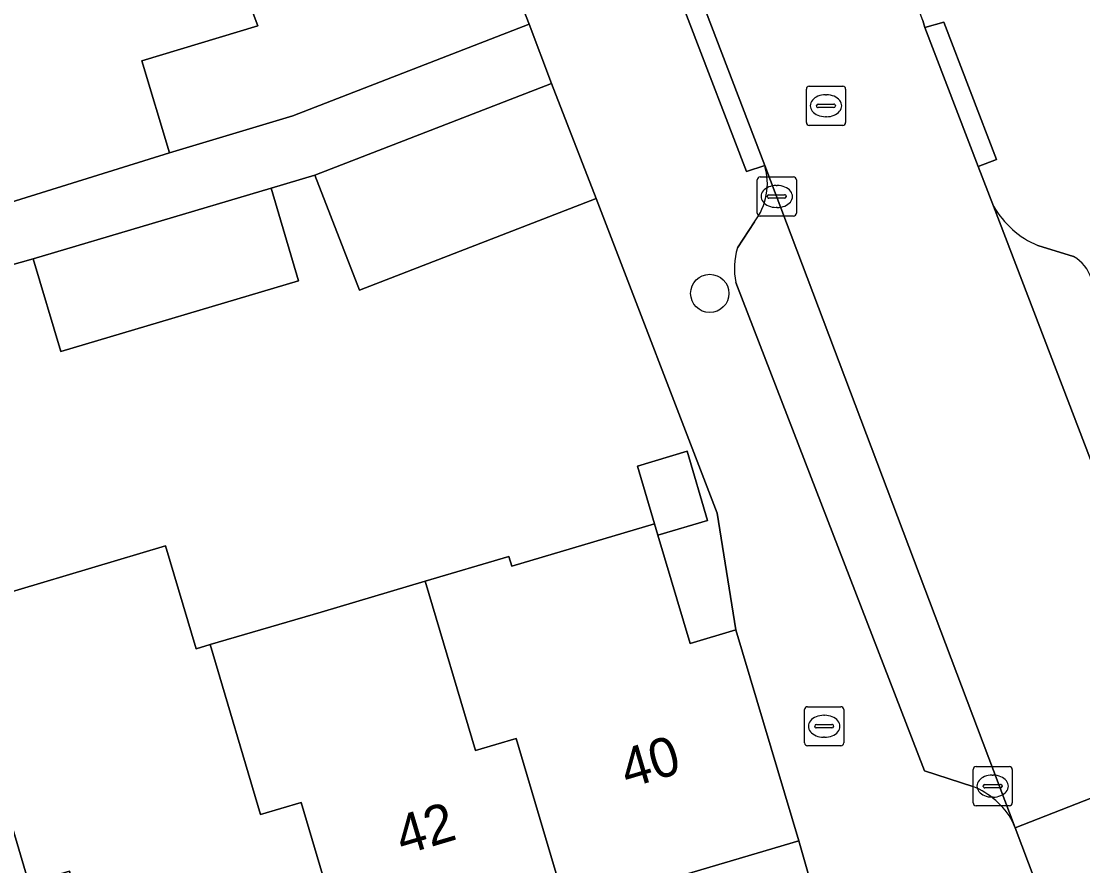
# Model space of a CAD drawing. Extents: x 162523 to 163266, y 381230 to 382050.
# Drawn here: x 162859.78 to 162886.88, y 381771.84 to 381793.41 of the extents above; entities that cross this region are included whole.
import ezdxf

# ---------------------------------------------------------------- set-up
doc = ezdxf.new("R2010")
doc.units = 0
for name, color, linetype in [('IMGEO_Boom', 7, 'Continuous'), ('IMGEO_Brandkraan', 7, 'Continuous'), ('IMGEO_Erf', 7, 'Continuous'), ('IMGEO_Kolk', 7, 'Continuous'), ('IMGEO_Muur', 7, 'Continuous'), ('IMGEO_Pand', 7, 'Continuous'), ('IMGEO_Pand_nummerreeks', 7, 'Continuous'), ('IMGEO_Parkeervlak_open', 7, 'Continuous'), ('IMGEO_Rijbaan_lokaal_open', 7, 'Continuous'), ('IMGEO_Rioolput', 7, 'Continuous'), ('IMGEO_Voetpad_open', 7, 'Continuous')]:
    doc.layers.add(name, color=color, linetype=linetype)

msp = doc.modelspace()

# ---------------------------------------------------------------- linework, layer by layer
at = {"layer": 'IMGEO_Boom'}
msp.add_circle((162877.355, 381786.459), 0.489, dxfattribs=at)
at = {"layer": 'IMGEO_Brandkraan'}
for p, q in [((162879.774, 381774.979), (162879.774, 381775.831)), ((162879.849, 381775.905), (162880.701, 381775.905)), ((162880.262, 381775.685), (162880.287, 381775.685)), ((162880.775, 381775.831), (162880.775, 381774.979)), ((162880.033, 381775.399), (162880.033, 381775.411)), ((162880.076, 381775.448), (162880.474, 381775.448)), ((162880.517, 381775.411), (162880.517, 381775.399)), ((162880.471, 381775.362), (162880.073, 381775.362)), ((162880.701, 381774.905), (162879.849, 381774.905)), ((162880.285, 381775.125), (162880.26, 381775.125))]:
    msp.add_line(p, q, dxfattribs=at)
for points in [[(162879.774, 381774.979), (162879.774, 381775.831)], [(162879.849, 381775.905), (162880.701, 381775.905)], [(162880.775, 381775.831), (162880.775, 381774.979)], [(162880.701, 381774.905), (162879.849, 381774.905)]]:
    msp.add_lwpolyline(points, dxfattribs=at)
for centre, radius, start, end in [((162879.851, 381775.829), 0.0765, 91.552, 178.448), ((162879.851, 381775.829), 0.0765, 91.552, 178.448), ((162880.699, 381775.829), 0.0765, 1.552, 88.448), ((162880.699, 381775.829), 0.0765, 1.552, 88.448), ((162880.073, 381775.408), 0.0403, 85.8775, 175.7526), ((162880.07, 381775.398), 0.0366, 178.938, 274.7102), ((162880.474, 381775.405), 0.043, 264.8664, 352.4533), ((162880.478, 381775.41), 0.0386, 1.7309, 96.639), ((162879.851, 381774.981), 0.0765, 181.552, 268.448), ((162879.851, 381774.981), 0.0765, 181.552, 268.448), ((162880.699, 381774.981), 0.0765, 271.552, 358.448), ((162880.699, 381774.981), 0.0765, 271.552, 358.448)]:
    msp.add_arc(centre, radius, start, end, dxfattribs=at)
for centre, major_axis, ratio, start_param, end_param in [((162880.261, 381775.405), (-0.387, 0.002), 0.722429, 4.712389, 7.853982), ((162880.286, 381775.405), (-0.39, 0.002), 0.717154, 1.570796, 4.712389)]:
    msp.add_ellipse(centre, major_axis=major_axis, ratio=ratio, start_param=start_param, end_param=end_param, dxfattribs=at)
at = {"layer": 'IMGEO_Erf'}
for points in [[(162858.449, 381788.462), (162863.565, 381790.046), (162862.855, 381792.401), (162865.822, 381793.297), (162865.57, 381793.947), (162871.6, 381796.286), (162865.905, 381810.851)], [(162857.816, 381778.33), (162863.463, 381780.009), (162864.243, 381777.386), (162864.6, 381777.49), (162867.434, 381778.318), (162870.088, 381779.107), (162872.226, 381779.742), (162872.299, 381779.496), (162875.944, 381780.579), (162875.507, 381782.051), (162876.776, 381782.428), (162877.3, 381780.664), (162876.031, 381780.287), (162876.852, 381777.523), (162878.023, 381777.872), (162877.543, 381780.848), (162874.457, 381788.886), (162868.417, 381786.543), (162867.278, 381789.481), (162866.157, 381789.148), (162866.86, 381786.782), (162860.792, 381784.978), (162860.088, 381787.344), (162845.75, 381783.296)], [(162880.883, 381768.073), (162879.625, 381772.482), (162873.71, 381770.724)]]:
    msp.add_lwpolyline(points, dxfattribs=at)
at = {"layer": 'IMGEO_Kolk'}
for p, q in [((162878.564, 381788.509), (162878.564, 381789.361)), ((162878.639, 381789.435), (162879.491, 381789.435)), ((162879.565, 381789.361), (162879.565, 381788.509)), ((162878.866, 381788.978), (162879.264, 381788.978)), ((162879.052, 381789.215), (162879.077, 381789.215)), ((162878.823, 381788.929), (162878.823, 381788.941)), ((162879.261, 381788.892), (162878.863, 381788.892)), ((162879.307, 381788.941), (162879.307, 381788.929)), ((162879.491, 381788.435), (162878.639, 381788.435)), ((162879.075, 381788.655), (162879.05, 381788.655)), ((162884.15, 381774.376), (162885.002, 381774.376)), ((162884.075, 381773.45), (162884.075, 381774.302)), ((162884.563, 381774.156), (162884.588, 381774.156)), ((162885.076, 381774.302), (162885.076, 381773.45)), ((162884.334, 381773.87), (162884.334, 381773.882)), ((162884.772, 381773.833), (162884.374, 381773.833)), ((162884.377, 381773.919), (162884.775, 381773.919)), ((162884.818, 381773.882), (162884.818, 381773.87)), ((162884.586, 381773.596), (162884.561, 381773.596)), ((162885.002, 381773.376), (162884.15, 381773.376))]:
    msp.add_line(p, q, dxfattribs=at)
for points in [[(162878.564, 381788.509), (162878.564, 381789.361)], [(162878.639, 381789.435), (162879.491, 381789.435)], [(162879.565, 381789.361), (162879.565, 381788.509)], [(162879.491, 381788.435), (162878.639, 381788.435)], [(162884.15, 381774.376), (162885.002, 381774.376)], [(162884.075, 381773.45), (162884.075, 381774.302)], [(162885.076, 381774.302), (162885.076, 381773.45)], [(162885.002, 381773.376), (162884.15, 381773.376)]]:
    msp.add_lwpolyline(points, dxfattribs=at)
for centre, radius, start, end in [((162878.641, 381789.359), 0.0765, 91.552, 178.448), ((162878.641, 381789.359), 0.0765, 91.552, 178.448), ((162879.489, 381789.359), 0.0765, 1.552, 88.448), ((162879.489, 381789.359), 0.0765, 1.552, 88.448), ((162878.863, 381788.938), 0.0403, 85.8775, 175.7526), ((162879.268, 381788.94), 0.0386, 1.7309, 96.639), ((162878.86, 381788.928), 0.0366, 178.938, 274.7102), ((162879.264, 381788.935), 0.043, 264.8664, 352.4533), ((162878.641, 381788.511), 0.0765, 181.552, 268.448), ((162878.641, 381788.511), 0.0765, 181.552, 268.448), ((162879.489, 381788.511), 0.0765, 271.552, 358.448), ((162879.489, 381788.511), 0.0765, 271.552, 358.448), ((162884.152, 381774.3), 0.0765, 91.552, 178.448), ((162884.152, 381774.3), 0.0765, 91.552, 178.448), ((162885, 381774.3), 0.0765, 1.552, 88.448), ((162885, 381774.3), 0.0765, 1.552, 88.448), ((162884.374, 381773.879), 0.0403, 85.8775, 175.7526), ((162884.371, 381773.869), 0.0366, 178.938, 274.7102), ((162884.775, 381773.876), 0.043, 264.8664, 352.4533), ((162884.779, 381773.881), 0.0386, 1.7309, 96.639), ((162884.152, 381773.452), 0.0765, 181.552, 268.448), ((162884.152, 381773.452), 0.0765, 181.552, 268.448), ((162885, 381773.452), 0.0765, 271.552, 358.448), ((162885, 381773.452), 0.0765, 271.552, 358.448)]:
    msp.add_arc(centre, radius, start, end, dxfattribs=at)
for centre, major_axis, ratio, start_param, end_param in [((162879.051, 381788.935), (-0.387, 0.002), 0.722429, 4.712389, 7.853982), ((162879.076, 381788.935), (-0.39, 0.002), 0.717154, 1.570796, 4.712389), ((162884.562, 381773.876), (-0.387, 0.002), 0.722429, 4.712389, 7.853982), ((162884.587, 381773.876), (-0.39, 0.002), 0.717154, 1.570796, 4.712389)]:
    msp.add_ellipse(centre, major_axis=major_axis, ratio=ratio, start_param=start_param, end_param=end_param, dxfattribs=at)
at = {"layer": 'IMGEO_Muur'}
msp.add_lwpolyline([(162874.457, 381788.886), (162877.543, 381780.848)], dxfattribs=at)
at = {"layer": 'IMGEO_Pand'}
for points in [[(162871.6, 381796.286), (162865.57, 381793.947), (162865.822, 381793.297), (162862.855, 381792.401), (162863.565, 381790.046), (162866.714, 381790.997), (162872.744, 381793.336)], [(162874.457, 381788.886), (162873.318, 381791.824), (162867.278, 381789.481), (162868.417, 381786.543)], [(162866.157, 381789.148), (162860.088, 381787.344), (162860.792, 381784.978), (162866.86, 381786.782)], [(162875.507, 381782.051), (162875.944, 381780.579), (162876.031, 381780.287), (162877.3, 381780.664), (162876.776, 381782.428)], [(162878.023, 381777.872), (162876.852, 381777.523), (162876.031, 381780.287), (162875.944, 381780.579), (162872.299, 381779.496), (162872.226, 381779.742), (162870.088, 381779.107), (162871.376, 381774.783), (162872.413, 381775.091), (162873.71, 381770.724), (162879.625, 381772.482)], [(162866.925, 381773.461), (162865.888, 381773.153), (162864.6, 381777.49), (162864.243, 381777.386), (162863.463, 381780.009), (162857.816, 381778.33), (162858.587, 381775.734), (162858.681, 381775.761), (162859.977, 381771.397), (162861.014, 381771.705), (162862.311, 381767.336), (162868.222, 381769.093)], [(162868.222, 381769.093), (162873.71, 381770.724), (162872.413, 381775.091), (162871.376, 381774.783), (162870.088, 381779.107), (162867.434, 381778.318), (162864.6, 381777.49), (162865.888, 381773.153), (162866.925, 381773.461)], [(162861.014, 381771.705), (162859.977, 381771.397), (162858.681, 381775.761), (162858.587, 381775.734), (162852.934, 381774.082), (162853.863, 381770.955), (162855.027, 381771.301), (162856.701, 381765.669), (162862.311, 381767.336)]]:
    msp.add_lwpolyline(points, close=True, dxfattribs=at)
at = {"layer": 'IMGEO_Parkeervlak_open'}
for points in [[(162885.083, 381772.975), (162885.152, 381772.812), (162878.756, 381789.728)], [(162884.595, 381788.686), (162887.796, 381780.324)], [(162878.494, 381788.284), (162878.061, 381787.625)], [(162886.641, 381787.403), (162885.727, 381787.685)], [(162878.021, 381786.736), (162882.837, 381774.263), (162884.071, 381773.869)]]:
    msp.add_lwpolyline(points, dxfattribs=at)
for centre, radius, start, end in [((162877.204, 381789.264), 1.62, 322.7769, 16.6553), ((162886.668, 381789.889), 2.397, 210.1397, 246.8892), ((162879.746, 381787.104), 1.764, 162.8097, 192.0378), ((162886.158, 381786.552), 0.978, 16.5643, 60.437), ((162883.317, 381771.995), 2.02, 29.0152, 68.0701)]:
    msp.add_arc(centre, radius, start, end, dxfattribs=at)
at = {"layer": 'IMGEO_Rijbaan_lokaal_open'}
for points in [[(162869.383, 381813.839), (162869.461, 381813.644), (162869.551, 381813.335), (162875.697, 381797.712), (162875.771, 381797.545), (162878.756, 381789.728), (162885.152, 381772.812), (162889.996, 381774.708), (162888.916, 381777.507), (162887.796, 381780.324), (162884.595, 381788.686), (162884.207, 381789.697), (162882.845, 381793.25), (162882.793, 381793.432), (162870.073, 381826.813)], [(162889.996, 381774.708), (162885.152, 381772.812)], [(162885.152, 381772.812), (162886.001, 381770.556)]]:
    msp.add_lwpolyline(points, dxfattribs=at)
at = {"layer": 'IMGEO_Rioolput'}
for p, q in [((162879.82, 381790.826), (162879.82, 381791.678)), ((162879.895, 381791.752), (162880.747, 381791.752)), ((162880.821, 381791.678), (162880.821, 381790.826)), ((162880.308, 381791.532), (162880.333, 381791.532)), ((162880.079, 381791.246), (162880.079, 381791.258)), ((162880.517, 381791.209), (162880.119, 381791.209)), ((162880.122, 381791.295), (162880.52, 381791.295)), ((162880.563, 381791.258), (162880.563, 381791.246)), ((162880.331, 381790.972), (162880.306, 381790.972)), ((162880.747, 381790.752), (162879.895, 381790.752))]:
    msp.add_line(p, q, dxfattribs=at)
for points in [[(162879.82, 381790.826), (162879.82, 381791.678)], [(162879.895, 381791.752), (162880.747, 381791.752)], [(162880.821, 381791.678), (162880.821, 381790.826)], [(162880.747, 381790.752), (162879.895, 381790.752)]]:
    msp.add_lwpolyline(points, dxfattribs=at)
for centre, radius, start, end in [((162879.897, 381791.676), 0.0765, 91.552, 178.448), ((162879.897, 381791.676), 0.0765, 91.552, 178.448), ((162880.745, 381791.676), 0.0765, 1.552, 88.448), ((162880.745, 381791.676), 0.0765, 1.552, 88.448), ((162880.119, 381791.255), 0.0403, 85.8775, 175.7526), ((162880.116, 381791.245), 0.0366, 178.938, 274.7102), ((162880.52, 381791.252), 0.043, 264.8664, 352.4533), ((162880.524, 381791.257), 0.0386, 1.7309, 96.639), ((162879.897, 381790.828), 0.0765, 181.552, 268.448), ((162879.897, 381790.828), 0.0765, 181.552, 268.448), ((162880.745, 381790.828), 0.0765, 271.552, 358.448), ((162880.745, 381790.828), 0.0765, 271.552, 358.448)]:
    msp.add_arc(centre, radius, start, end, dxfattribs=at)
for centre, major_axis, ratio, start_param, end_param in [((162880.307, 381791.252), (-0.387, 0.002), 0.722429, 4.712389, 7.853982), ((162880.332, 381791.252), (-0.39, 0.002), 0.717154, 1.570796, 4.712389)]:
    msp.add_ellipse(centre, major_axis=major_axis, ratio=ratio, start_param=start_param, end_param=end_param, dxfattribs=at)
at = {"layer": 'IMGEO_Voetpad_open'}
for points in [[(162865.905, 381810.851), (162871.6, 381796.286), (162872.744, 381793.336), (162873.318, 381791.824), (162874.457, 381788.886), (162877.543, 381780.848), (162878.023, 381777.872), (162879.625, 381772.482), (162880.883, 381768.073), (162886.293, 381769.608)], [(162878.756, 381789.728), (162878.288, 381789.571), (162875.311, 381797.348)], [(162816.674, 381759.751), (162812.653, 381773.393), (162815.076, 381774.107), (162819.635, 381775.433), (162845.75, 381783.296), (162860.088, 381787.344), (162866.157, 381789.148), (162867.278, 381789.481), (162873.318, 381791.824), (162872.744, 381793.336), (162866.714, 381790.997), (162863.565, 381790.046), (162858.449, 381788.462), (162855.362, 381787.531), (162851.945, 381786.499), (162851.961, 381786.441), (162851.386, 381786.263), (162831.371, 381780.416), (162831.384, 381780.374), (162828.297, 381779.443), (162825.144, 381778.491), (162825.115, 381778.589), (162807.109, 381773.329)], [(162882.793, 381793.432), (162882.845, 381793.25), (162883.326, 381793.39), (162884.673, 381789.877), (162884.207, 381789.697), (162884.595, 381788.686)], [(162878.061, 381787.625), (162878.494, 381788.284)], [(162885.727, 381787.685), (162886.641, 381787.403)], [(162884.071, 381773.869), (162882.837, 381774.263), (162878.021, 381786.736)], [(162886.001, 381770.556), (162885.152, 381772.812), (162885.083, 381772.975)]]:
    msp.add_lwpolyline(points, dxfattribs=at)
for points in [[(162878.756, 381789.728), (162875.771, 381797.545), (162875.311, 381797.348), (162878.288, 381789.571)], [(162882.845, 381793.25), (162884.207, 381789.697), (162884.673, 381789.877), (162883.326, 381793.39)]]:
    msp.add_lwpolyline(points, close=True, dxfattribs=at)
for centre, radius, start, end in [((162877.204, 381789.264), 1.62, 322.7769, 16.6553), ((162886.668, 381789.889), 2.397, 210.1397, 246.8892), ((162879.746, 381787.104), 1.764, 162.8097, 192.0378), ((162886.158, 381786.552), 0.978, 16.5643, 60.437), ((162883.317, 381771.995), 2.02, 29.0152, 68.0701)]:
    msp.add_arc(centre, radius, start, end, dxfattribs=at)

# ---------------------------------------------------------------- texts
at = {"layer": 'IMGEO_Pand_nummerreeks'}
for s, rotation, p in [('40', 16.5528, (162875.252, 381773.811)), ('42', 16.5519, (162869.515, 381772.107))]:
    msp.add_text(s, height=1, rotation=rotation, dxfattribs=at).set_placement(p)

doc.saveas('drawing.dxf')
